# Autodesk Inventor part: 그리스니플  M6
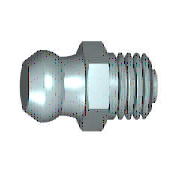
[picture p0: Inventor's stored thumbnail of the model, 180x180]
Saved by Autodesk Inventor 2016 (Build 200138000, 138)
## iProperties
IsCustomPart: 1
Created: 2012-02
Part Number: 그리스니플  M6
Material: 강철, 연강
Description: 그리스 니플에 대한 사양. 제I부: 버튼 머리 그리스 니플 유형 A
Document SubType Name: Modeling
Standard: IS 4009
Designer: mduedu
Standards Organization: IS
Language: ko-KR
Size Designation: M6 원추 짧은
Categories: <MemberInstance><Categories><Category DisplayName="기타 부품" InternalName="5aa15e00-363f-49f2-933f-16f664388e3f" Mnemonic="OTHER"><Category DisplayName="그리스 부속품" I
Density: 1 g/cm^3
Appearance: 강철
Author: mduedu
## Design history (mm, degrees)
sketch "스케치1"
  geometry: L1 (-9.8, 0)-(-9.8, 2.25); L2 (-9.8, 2.25)-(-8.055, 3.194); L3 (-9.8, 0)-(6.2, 0); L4 (6.2, 0)-(6.2, 1.5); L5 (6.2, 1.5)-(5.5, 1.5); L6 (5.5, 1.5)-(5.5, 3); L7 (5.5, 3)-(0, 3); L8 (-13, 0)-(9.4, 0) reference; L9 (0, -1.725)-(0, 10.35) reference; L10 (-3, 3.5)-(0, 3.5); L11 (0, 3.5)-(0, 3); A1 r 3.25 centre (-7.455, 0) between (-5.573, 2.65) and (-8.055, 3.194); A2 r 6 centre (-6.12, 8.625) between (-5.573, 2.65) and (-3, 3.5)
  constraints: 18 end point, 5 perpendicular, 4 point on circle, 2 centre point, 2 parallel, 2 point on line, 1 collinear, 1 vertical
  dimensions: "d0" = 16 distance between parallel lines of L1 L4 (= GL); "d1" = 5.3 diameter of A1.start L3 (= KGB2); "d2" = 0.7 distance between parallel lines of L4 L6 (= PHH); "d3" = 3 diameter of L5 L3 (= 0.5 x NND); "d4" = 6 diameter of L7 L3 (= NND); "d5" = 6.5 dimension on A1 L3 (= KR); "d6" = 4.5 diameter of L1.end L3 (= KGB1); "d7" = 6 radius of A2 (= RBN); "d11" = 7 diameter of L10.start L3 (= SW); "d14" = 3 distance of L10.start L10.end (= KOH); "d15" = 5.5 distance between parallel lines of L6 L11 (= NLG); "d61" = 8.05479 distance from line of L9 L2.end (computed from KGB1, KR, PHH, GL, NLG, VERS); "d62" = 7.45479 distance from line of L9 A1.centre (computed from NLG, GL, PHH, KR, KGB1)
revolve "본체" sketch "스케치1" stored, may be unused: angle "d25" = 90 deg
sketch "스케치2"
  geometry: L1 (2.021, 3.5)-(4.041, 0); L2 (4.041, 0)-(2.021, -3.5); L3 (2.021, -3.5)-(-2.021, -3.5); L4 (-2.021, -3.5)-(-4.041, 0); L5 (-4.041, 0)-(-2.021, 3.5); L6 (-2.021, 3.5)-(2.021, 3.5); C1 r 3.5 at (0, 0) reference; 1 further point
  constraints: 12 end point, 1 coincident, 1 horizontal, 1 tangent, 11 other
extrude "머리" join sketch "스케치2" distance "d17" = 3 (= KOH); taper "d18" = 0 deg
sketch "스케치3"
  geometry: L1 (2.687, 4.041)-(3, 4.041); L2 (3, 4.041)-(3, 3.5); L3 (3, 3.5)-(2.687, 4.041); L4 (0.313, 4.041)-(0, 4.041); L5 (0, 4.041)-(0, 3.5); L6 (0, 3.5)-(0.313, 4.041); L7 (3.6, 0)-(-0.6, 0) reference; L8 (0, 4.041)-(0, 2.021) reference; L9 (0, 4.041)-(3, 4.041) reference; L10 (3, 3.031)-(3, 4.041) reference
  constraints: 12 end point, 4 collinear, 3 perpendicular, 1 horizontal
  dimensions: "d19" = 3.5 distance from line of L5.end L7 (= 0.5 x SW); "d20" = 3.5 distance from line of L2.end L7 (= 0.5 x SW); "d21" = 30 deg angle of L6 L5; "d22" = 30 deg angle of L2 L3
revolve "모따기1" sketch "스케치3" stored, may be unused: angle "d56" = 90 deg
body "Solid1"
fillet "모깎기1" dims "d8" = 0.2 (= RR)
feature "스레드1" dims "d9" = 4.88655 (= NLG - GAL), "d10" = 0
chamfer "모따기2" distance "d23" = 0.61345 (= -0.5 x GD1 + 0.5 x NND); stored, may be unused: angle "d24" = 45 deg, second distance "d59" = 0.61345 (= -0.5 x GD1 + 0.5 x NND)
other parameters: "NLG" = 5.5 [user parameter; used in 4 equation terms], "GL" = 16 [user parameter; used in 3 equation terms], "NND" = 6 [user parameter; used in 4 equation terms], "KGB1" = 4.5 [user parameter; used in 3 equation terms], "KGB2" = 5.3 [user parameter; used in 1 equation term], "VERS" = 0.6 [user parameter; used in 1 equation term], "KR" = 6.5 [user parameter; used in 3 equation terms], "RBN" = 6 [user parameter; used in 1 equation term], "SW" = 7 [user parameter; used in 3 equation terms], "KOH" = 3 [user parameter; used in 2 equation terms], "GAL" = 0.61345 (= 0.61345 x PTC) [user parameter; used in 1 equation term], "FAWI" = 45 deg [user parameter], "PHH" = 0.7 [user parameter; used in 3 equation terms], "GD1" = 4.7731 (= THREADDIA - 1.2269 x PTC) [user parameter; used in 2 equation terms], "RR" = 0.2 [user parameter; used in 1 equation term], "d12" = 0, "d13" = 0, "GUL" = 0.61345 (= 0.61345 x PTC) [user parameter], "DULO" = 1.5 [user parameter], "PTC" = 1 [user parameter; used in 4 equation terms], "GEL" = 5.5 [user parameter], "THREADDIA" = 6 [user parameter; used in 1 equation term], "TOA" = 30 deg [user parameter]
